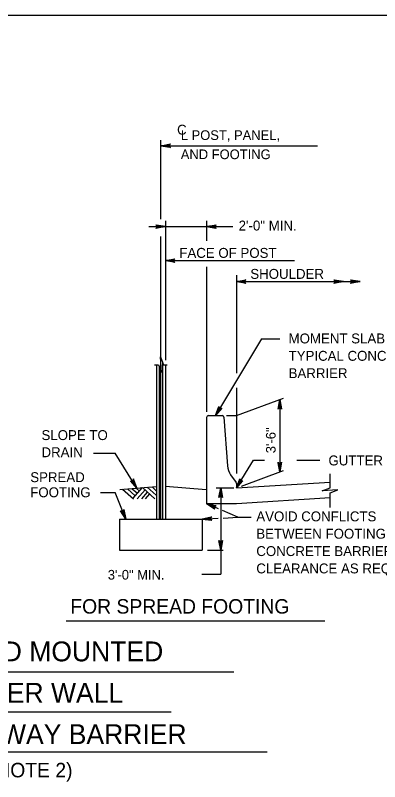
# Model space of a CAD drawing. Extents: x 3761 to 5458, y -616 to 1166.
# Drawn here: x 5067.4 to 5180.3, y 319.4 to 556.7 of the extents above; entities that cross this region are included whole.
import ezdxf

# ---------------------------------------------------------------- set-up
doc = ezdxf.new("R2010")
doc.units = 0
doc.layers.add('1', color=7, linetype='Continuous')
doc.layers.add('2', color=7, linetype='Continuous')

msp = doc.modelspace()

# ---------------------------------------------------------------- linework, layer by layer
at = {"layer": '1'}
for p, q in [((5112.5, 493.55), (5112.5, 518.08)), ((5112.5, 516.32), (5161.05, 516.32)), ((5108.78, 491.27), (5134.78, 491.27)), ((5113.88, 493.12), (5113.88, 449.95)), ((5126.68, 493.12), (5126.68, 486.84)), ((5112.5, 400.76), (5112.5, 488.23)), ((5113.88, 480.75), (5153.93, 480.75)), ((5126.68, 478.78), (5126.68, 433.92)), ((5135.88, 476.23), (5135.88, 445.86)), ((5135.88, 474.25), (5174.21, 474.25)), ((5143.71, 456.56), (5129.38, 432.76)), ((5143.71, 456.56), (5149.36, 456.56)), ((5110.48, 448.53), (5111.74, 448.53)), ((5111.12, 448.53), (5111.12, 400.76)), ((5112.98, 449.47), (5112.98, 400.76)), ((5113.34, 448.53), (5114.39, 448.53)), ((5113.88, 448.53), (5113.88, 400.76)), ((5112.01, 447.87), (5112.01, 400.76)), ((5135.88, 441.35), (5135.88, 414.89)), ((5135.88, 432.76), (5150.45, 438.13)), ((5149.36, 437.73), (5149.36, 415.33)), ((5126.68, 432.23), (5126.68, 405.56)), ((5127.21, 432.76), (5131.52, 432.76)), ((5132.05, 432.27), (5133.11, 417.2)), ((5132.8, 432.76), (5135.88, 432.76)), ((5091.57, 421.13), (5098.34, 421.13)), ((5105.08, 410.32), (5098.34, 421.13)), ((5135.88, 410.36), (5141.23, 418.94)), ((5141.23, 418.94), (5144.59, 418.94)), ((5154.65, 418.94), (5161.81, 418.94)), ((5137.47, 410.95), (5150.49, 415.74)), ((5134.09, 414.47), (5135.78, 412.1)), ((5164.91, 410.45), (5164.91, 414.79)), ((5099.72, 409.87), (5111.12, 410.82)), ((5103.8, 407.14), (5106.79, 410.5)), ((5110.66, 407.05), (5106.79, 410.5)), ((5111.07, 408.1), (5108.28, 410.58)), ((5111.07, 409.52), (5109.78, 410.67)), ((5126.49, 409.77), (5113.88, 410.82)), ((5135.88, 410.36), (5164.91, 412.2)), ((5135.88, 411.79), (5135.88, 410.36)), ((5093.79, 408.97), (5098.34, 408.97)), ((5101.6, 400.76), (5098.34, 408.97)), ((5100.63, 409.97), (5103.98, 406.98)), ((5102.12, 410.05), (5104.5, 407.93)), ((5103.62, 410.14), (5105.21, 408.72)), ((5104.95, 410.16), (5105.82, 409.38)), ((5105.13, 407.05), (5107.58, 409.79)), ((5106.55, 407.05), (5108.37, 409.09)), ((5107.75, 407.05), (5109.05, 408.51)), ((5129.65, 410.36), (5134.69, 410.36)), ((5130.43, 410.36), (5135.11, 410.36)), ((5131.04, 410.36), (5131.04, 383.64)), ((5164.91, 404.33), (5164.91, 408.85)), ((5135.88, 405.56), (5164.91, 407.4)), ((5126.68, 405.56), (5135.88, 405.56)), ((5125.3, 400.76), (5130.21, 401)), ((5131.84, 401.07), (5136.31, 401.29)), ((5136.31, 401.29), (5140.48, 401.29)), ((5099.7, 400.76), (5099.7, 391.16)), ((5099.7, 400.76), (5125.3, 400.76)), ((5125.3, 400.76), (5125.3, 391.16)), ((5099.7, 391.16), (5125.3, 391.16)), ((5126.89, 391.16), (5131.79, 391.16)), ((5125.21, 383.64), (5131.04, 383.64)), ((5083.12, 369.28), (5163.28, 369.28)), ((4989.29, 353.42), (5135.11, 353.42)), ((5007.44, 341.04), (5115.69, 341.04)), ((4977.63, 328.65), (5145.41, 328.65))]:
    msp.add_line(p, q, dxfattribs=at)
for points in [[(5112.5, 516.32), (5115.48, 516.88), (5115.25, 516.72), (5115.13, 516.52), (5115.1, 516.32), (5115.13, 516.12), (5115.25, 515.92), (5115.48, 515.76), (5112.5, 516.32), (5115.25, 515.92), (5115.13, 516.12), (5112.5, 516.32), (5115.1, 516.32), (5115.13, 516.52), (5112.5, 516.32), (5115.25, 516.72)], [(5113.88, 491.27), (5110.9, 490.71), (5111.01, 490.79), (5111.13, 490.87), (5111.19, 490.97), (5111.25, 491.07), (5111.26, 491.17), (5111.28, 491.27), (5111.26, 491.37), (5111.25, 491.47), (5111.19, 491.57), (5111.13, 491.67), (5111.01, 491.75), (5110.9, 491.83), (5113.88, 491.27), (5111.01, 491.75), (5111.13, 491.67), (5113.88, 491.27), (5111.19, 491.57), (5111.25, 491.47), (5113.88, 491.27), (5111.26, 491.37), (5111.28, 491.27), (5113.88, 491.27), (5111.26, 491.17), (5111.25, 491.07), (5113.88, 491.27), (5111.19, 490.97), (5111.13, 490.87), (5113.88, 491.27), (5111.01, 490.79)], [(5126.68, 491.27), (5129.66, 491.83), (5129.55, 491.75), (5129.43, 491.67), (5129.37, 491.57), (5129.31, 491.47), (5129.3, 491.37), (5129.28, 491.27), (5129.3, 491.17), (5129.31, 491.07), (5129.37, 490.97), (5129.43, 490.87), (5129.55, 490.79), (5129.66, 490.71), (5126.68, 491.27), (5129.55, 490.79), (5129.43, 490.87), (5126.68, 491.27), (5129.37, 490.97), (5129.31, 491.07), (5126.68, 491.27), (5129.3, 491.17), (5129.28, 491.27), (5126.68, 491.27), (5129.3, 491.37), (5129.31, 491.47), (5126.68, 491.27), (5129.37, 491.57), (5129.43, 491.67), (5126.68, 491.27), (5129.55, 491.75)], [(5113.88, 480.75), (5116.86, 481.31), (5116.63, 481.15), (5116.51, 480.95), (5116.48, 480.75), (5116.51, 480.55), (5116.63, 480.35), (5116.86, 480.19), (5113.88, 480.75), (5116.63, 480.35), (5116.51, 480.55), (5113.88, 480.75), (5116.48, 480.75), (5116.51, 480.95), (5113.88, 480.75), (5116.63, 481.15)], [(5135.88, 474.25), (5138.86, 474.81), (5138.63, 474.65), (5138.51, 474.45), (5138.48, 474.25), (5138.51, 474.05), (5138.63, 473.85), (5138.86, 473.69), (5135.88, 474.25), (5138.63, 473.85), (5138.51, 474.05), (5135.88, 474.25), (5138.48, 474.25), (5138.51, 474.45), (5135.88, 474.25), (5138.63, 474.65)], [(5169.09, 474.25), (5166.11, 473.69), (5166.22, 473.77), (5166.34, 473.85), (5166.4, 473.95), (5166.45, 474.05), (5166.47, 474.15), (5166.49, 474.25), (5166.47, 474.35), (5166.45, 474.45), (5166.4, 474.55), (5166.34, 474.65), (5166.22, 474.73), (5166.11, 474.81), (5169.09, 474.25), (5166.22, 474.73), (5166.34, 474.65), (5169.09, 474.25), (5166.4, 474.55), (5166.45, 474.45), (5169.09, 474.25), (5166.47, 474.35), (5166.49, 474.25), (5169.09, 474.25), (5166.47, 474.15), (5166.45, 474.05), (5169.09, 474.25), (5166.4, 473.95), (5166.34, 473.85), (5169.09, 474.25), (5166.22, 473.77)], [(5174.21, 474.25), (5171.23, 473.69), (5171.34, 473.77), (5171.46, 473.85), (5171.52, 473.95), (5171.57, 474.05), (5171.59, 474.15), (5171.61, 474.25), (5171.59, 474.35), (5171.57, 474.45), (5171.52, 474.55), (5171.46, 474.65), (5171.34, 474.73), (5171.23, 474.81), (5174.21, 474.25), (5171.34, 474.73), (5171.46, 474.65), (5174.21, 474.25), (5171.52, 474.55), (5171.57, 474.45), (5174.21, 474.25), (5171.59, 474.35), (5171.61, 474.25), (5174.21, 474.25), (5171.59, 474.15), (5171.57, 474.05), (5174.21, 474.25), (5171.52, 473.95), (5171.46, 473.85), (5174.21, 474.25), (5171.34, 473.77)], [(5111.74, 448.53), (5112.72, 446.13), (5112.42, 450.93), (5113.34, 448.53)], [(5149.36, 437.73), (5149.92, 434.75), (5149.84, 434.86), (5149.76, 434.98), (5149.66, 435.04), (5149.56, 435.09), (5149.46, 435.11), (5149.36, 435.13), (5149.26, 435.11), (5149.16, 435.09), (5149.06, 435.04), (5148.96, 434.98), (5148.88, 434.86), (5148.8, 434.75), (5149.36, 437.73), (5148.88, 434.86), (5148.96, 434.98), (5149.36, 437.73), (5149.06, 435.04), (5149.16, 435.09), (5149.36, 437.73), (5149.26, 435.11), (5149.36, 435.13), (5149.36, 437.73), (5149.46, 435.11), (5149.56, 435.09), (5149.36, 437.73), (5149.66, 435.04), (5149.76, 434.98), (5149.36, 437.73), (5149.84, 434.86)], [(5129.38, 432.76), (5130.44, 435.61), (5130.44, 435.47), (5130.45, 435.33), (5130.51, 435.23), (5130.56, 435.12), (5130.64, 435.06), (5130.72, 434.99), (5130.81, 434.96), (5130.91, 434.92), (5131.02, 434.92), (5131.14, 434.92), (5131.27, 434.97), (5131.39, 435.03), (5129.38, 432.76), (5131.27, 434.97), (5131.14, 434.92), (5129.38, 432.76), (5131.02, 434.92), (5130.91, 434.92), (5129.38, 432.76), (5130.81, 434.96), (5130.72, 434.99), (5129.38, 432.76), (5130.64, 435.06), (5130.56, 435.12), (5129.38, 432.76), (5130.51, 435.23), (5130.45, 435.33), (5129.38, 432.76), (5130.44, 435.47)], [(5149.36, 415.33), (5148.8, 418.31), (5148.88, 418.2), (5148.96, 418.08), (5149.06, 418.02), (5149.16, 417.96), (5149.26, 417.95), (5149.36, 417.93), (5149.46, 417.95), (5149.56, 417.96), (5149.66, 418.02), (5149.76, 418.08), (5149.84, 418.2), (5149.92, 418.31), (5149.36, 415.33), (5149.84, 418.2), (5149.76, 418.08), (5149.36, 415.33), (5149.66, 418.02), (5149.56, 417.96), (5149.36, 415.33), (5149.46, 417.95), (5149.36, 417.93), (5149.36, 415.33), (5149.26, 417.95), (5149.16, 417.96), (5149.36, 415.33), (5149.06, 418.02), (5148.96, 418.08), (5149.36, 415.33), (5148.88, 418.2)], [(5105.08, 410.32), (5103.99, 413.15), (5103.98, 413.01), (5103.97, 412.87), (5103.92, 412.77), (5103.87, 412.67), (5103.79, 412.6), (5103.71, 412.53), (5103.62, 412.49), (5103.53, 412.46), (5103.41, 412.45), (5103.29, 412.45), (5103.17, 412.51), (5103.04, 412.56), (5105.08, 410.32), (5103.17, 412.51), (5103.29, 412.45), (5105.08, 410.32), (5103.41, 412.45), (5103.53, 412.46), (5105.08, 410.32), (5103.62, 412.49), (5103.71, 412.53), (5105.08, 410.32), (5103.79, 412.6), (5103.87, 412.67), (5105.08, 410.32), (5103.92, 412.77), (5103.97, 412.87), (5105.08, 410.32), (5103.98, 413.01)], [(5135.88, 410.36), (5136.97, 413.2), (5136.98, 413.06), (5136.99, 412.92), (5137.04, 412.81), (5137.09, 412.71), (5137.17, 412.64), (5137.25, 412.58), (5137.34, 412.54), (5137.44, 412.5), (5137.55, 412.5), (5137.67, 412.5), (5137.8, 412.55), (5137.92, 412.61), (5135.88, 410.36), (5137.8, 412.55), (5137.67, 412.5), (5135.88, 410.36), (5137.55, 412.5), (5137.44, 412.5), (5135.88, 410.36), (5137.34, 412.54), (5137.25, 412.58), (5135.88, 410.36), (5137.17, 412.64), (5137.09, 412.71), (5135.88, 410.36), (5137.04, 412.81), (5136.99, 412.92), (5135.88, 410.36), (5136.98, 413.06)], [(5164.91, 408.85), (5167.31, 409.82), (5162.51, 409.53), (5164.91, 410.45)], [(5131.04, 410.36), (5131.6, 407.38), (5131.52, 407.5), (5131.44, 407.61), (5131.34, 407.67), (5131.24, 407.73), (5131.14, 407.75), (5131.04, 407.76), (5130.94, 407.75), (5130.84, 407.73), (5130.74, 407.67), (5130.64, 407.61), (5130.56, 407.5), (5130.48, 407.38), (5131.04, 410.36), (5130.56, 407.5), (5130.64, 407.61), (5131.04, 410.36), (5130.74, 407.67), (5130.84, 407.73), (5131.04, 410.36), (5130.94, 407.75), (5131.04, 407.76), (5131.04, 410.36), (5131.14, 407.75), (5131.24, 407.73), (5131.04, 410.36), (5131.34, 407.67), (5131.44, 407.61), (5131.04, 410.36), (5131.52, 407.5)], [(5101.6, 400.76), (5099.98, 403.33), (5100.09, 403.25), (5100.21, 403.18), (5100.32, 403.16), (5100.44, 403.14), (5100.54, 403.16), (5100.64, 403.18), (5100.72, 403.23), (5100.81, 403.29), (5100.88, 403.38), (5100.95, 403.47), (5100.98, 403.61), (5101.02, 403.74), (5101.6, 400.76), (5100.98, 403.61), (5100.95, 403.47), (5101.6, 400.76), (5100.88, 403.38), (5100.81, 403.29), (5101.6, 400.76), (5100.72, 403.23), (5100.64, 403.18), (5101.6, 400.76), (5100.54, 403.16), (5100.44, 403.14), (5101.6, 400.76), (5100.32, 403.16), (5100.21, 403.18), (5101.6, 400.76), (5100.09, 403.25)], [(5126.68, 405.56), (5129.63, 404.86), (5129.5, 404.84), (5129.36, 404.81), (5129.26, 404.75), (5129.17, 404.68), (5129.11, 404.59), (5129.06, 404.51), (5129.03, 404.41), (5129.01, 404.31), (5129.02, 404.2), (5129.03, 404.08), (5129.11, 403.96), (5129.18, 403.84), (5126.68, 405.56), (5129.11, 403.96), (5129.03, 404.08), (5126.68, 405.56), (5129.02, 404.2), (5129.01, 404.31), (5126.68, 405.56), (5129.03, 404.41), (5129.06, 404.51), (5126.68, 405.56), (5129.11, 404.59), (5129.17, 404.68), (5126.68, 405.56), (5129.26, 404.75), (5129.36, 404.81), (5126.68, 405.56), (5129.5, 404.84)], [(5130.3, 403.96), (5126.68, 405.56)], [(5136.31, 401.29), (5131.56, 403.4)], [(5125.3, 400.76), (5128.25, 401.46), (5128.14, 401.38), (5128.03, 401.29), (5127.97, 401.19), (5127.92, 401.09), (5127.91, 400.99), (5127.89, 400.89), (5127.92, 400.79), (5127.94, 400.69), (5128, 400.59), (5128.07, 400.5), (5128.18, 400.42), (5128.3, 400.35), (5125.3, 400.76), (5128.18, 400.42), (5128.07, 400.5), (5125.3, 400.76), (5128, 400.59), (5127.94, 400.69), (5125.3, 400.76), (5127.92, 400.79), (5127.89, 400.89), (5125.3, 400.76), (5127.91, 400.99), (5127.92, 401.09), (5125.3, 400.76), (5127.97, 401.19), (5128.03, 401.29), (5125.3, 400.76), (5128.14, 401.38)], [(5131.04, 391.16), (5130.48, 394.15), (5130.56, 394.03), (5130.64, 393.92), (5130.74, 393.86), (5130.84, 393.8), (5130.94, 393.78), (5131.04, 393.76), (5131.14, 393.78), (5131.24, 393.8), (5131.34, 393.86), (5131.44, 393.92), (5131.52, 394.03), (5131.6, 394.15), (5131.04, 391.16), (5131.52, 394.03), (5131.44, 393.92), (5131.04, 391.16), (5131.34, 393.86), (5131.24, 393.8), (5131.04, 391.16), (5131.14, 393.78), (5131.04, 393.76), (5131.04, 391.16), (5130.94, 393.78), (5130.84, 393.8), (5131.04, 391.16), (5130.74, 393.86), (5130.64, 393.92), (5131.04, 391.16), (5130.56, 394.03)]]:
    msp.add_lwpolyline(points, dxfattribs=at)
for centre, radius, start, end in [((5127.21, 432.23), 0.533, 90, 180), ((5131.52, 432.23), 0.533, 4.0219, 90), ((5138.43, 417.57), 5.33, 184.0219, 215.5414), ((5135.35, 411.79), 0.533, 0, 35.5414)]:
    msp.add_arc(centre, radius, start, end, dxfattribs=at)
at = {"layer": '2'}
msp.add_line((4642.34, 556.69), (5428.34, 556.69), dxfattribs=at)

# ---------------------------------------------------------------- texts
at = {"layer": '1'}
for s, height, p in [('C', 3.07, (5117.51, 519.74)), ('L POST, PANEL,', 3, (5118.66, 518.1)), ('AND FOOTING', 3, (5118.66, 512.17)), ('2\'-0" MIN.', 3.072, (5136.59, 490.07)), ('FACE OF POST', 3.0721, (5118.21, 481.61)), ('SHOULDER', 3.072, (5140.21, 475.11)), ('MOMENT SLAB WITH', 3.0721, (5152.08, 455.12)), ('TYPICAL CONCRETE', 3.0721, (5152.08, 449.74)), ('BARRIER', 3.072, (5152.08, 444.37)), ('SLOPE TO', 3.072, (5075.49, 425.2)), ('DRAIN', 3.072, (5075.49, 419.89)), ('GUTTER LINE', 3.0721, (5164.44, 417.35)), ('SPREAD', 3.072, (5072, 412.17)), ('FOOTING', 3.072, (5072, 407.5)), ('AVOID CONFLICTS', 3.0721, (5142.07, 400.04)), ('BETWEEN FOOTING AND', 3.0721, (5142.07, 394.67)), ('CONCRETE BARRIER, INCREASE', 3.0721, (5142.07, 389.29)), ('CLEARANCE AS REQUIRED', 3.0721, (5142.07, 383.92)), ('3\'-0" MIN.', 3, (5096.04, 382)), ('FOR SPREAD FOOTING', 4.48, (5084.42, 371.47)), ('SECTION - GROUND MOUNTED', 6.1439, (4989.08, 356.7)), ('SOUND BARRIER WALL', 6.1439, (5007.68, 343.89)), ('ADJACENT TO ROADWAY BARRIER', 6.1439, (4979.86, 331.08)), ('OPTION 2 (SEE NOTE 2)', 4.48, (5016.2, 320.79))]:
    msp.add_text(s, height=height, dxfattribs=at).set_placement(p)
msp.add_text('3\'-6"', height=3, rotation=90, dxfattribs=at).set_placement((5148.06, 421.12))

doc.saveas('drawing.dxf')
